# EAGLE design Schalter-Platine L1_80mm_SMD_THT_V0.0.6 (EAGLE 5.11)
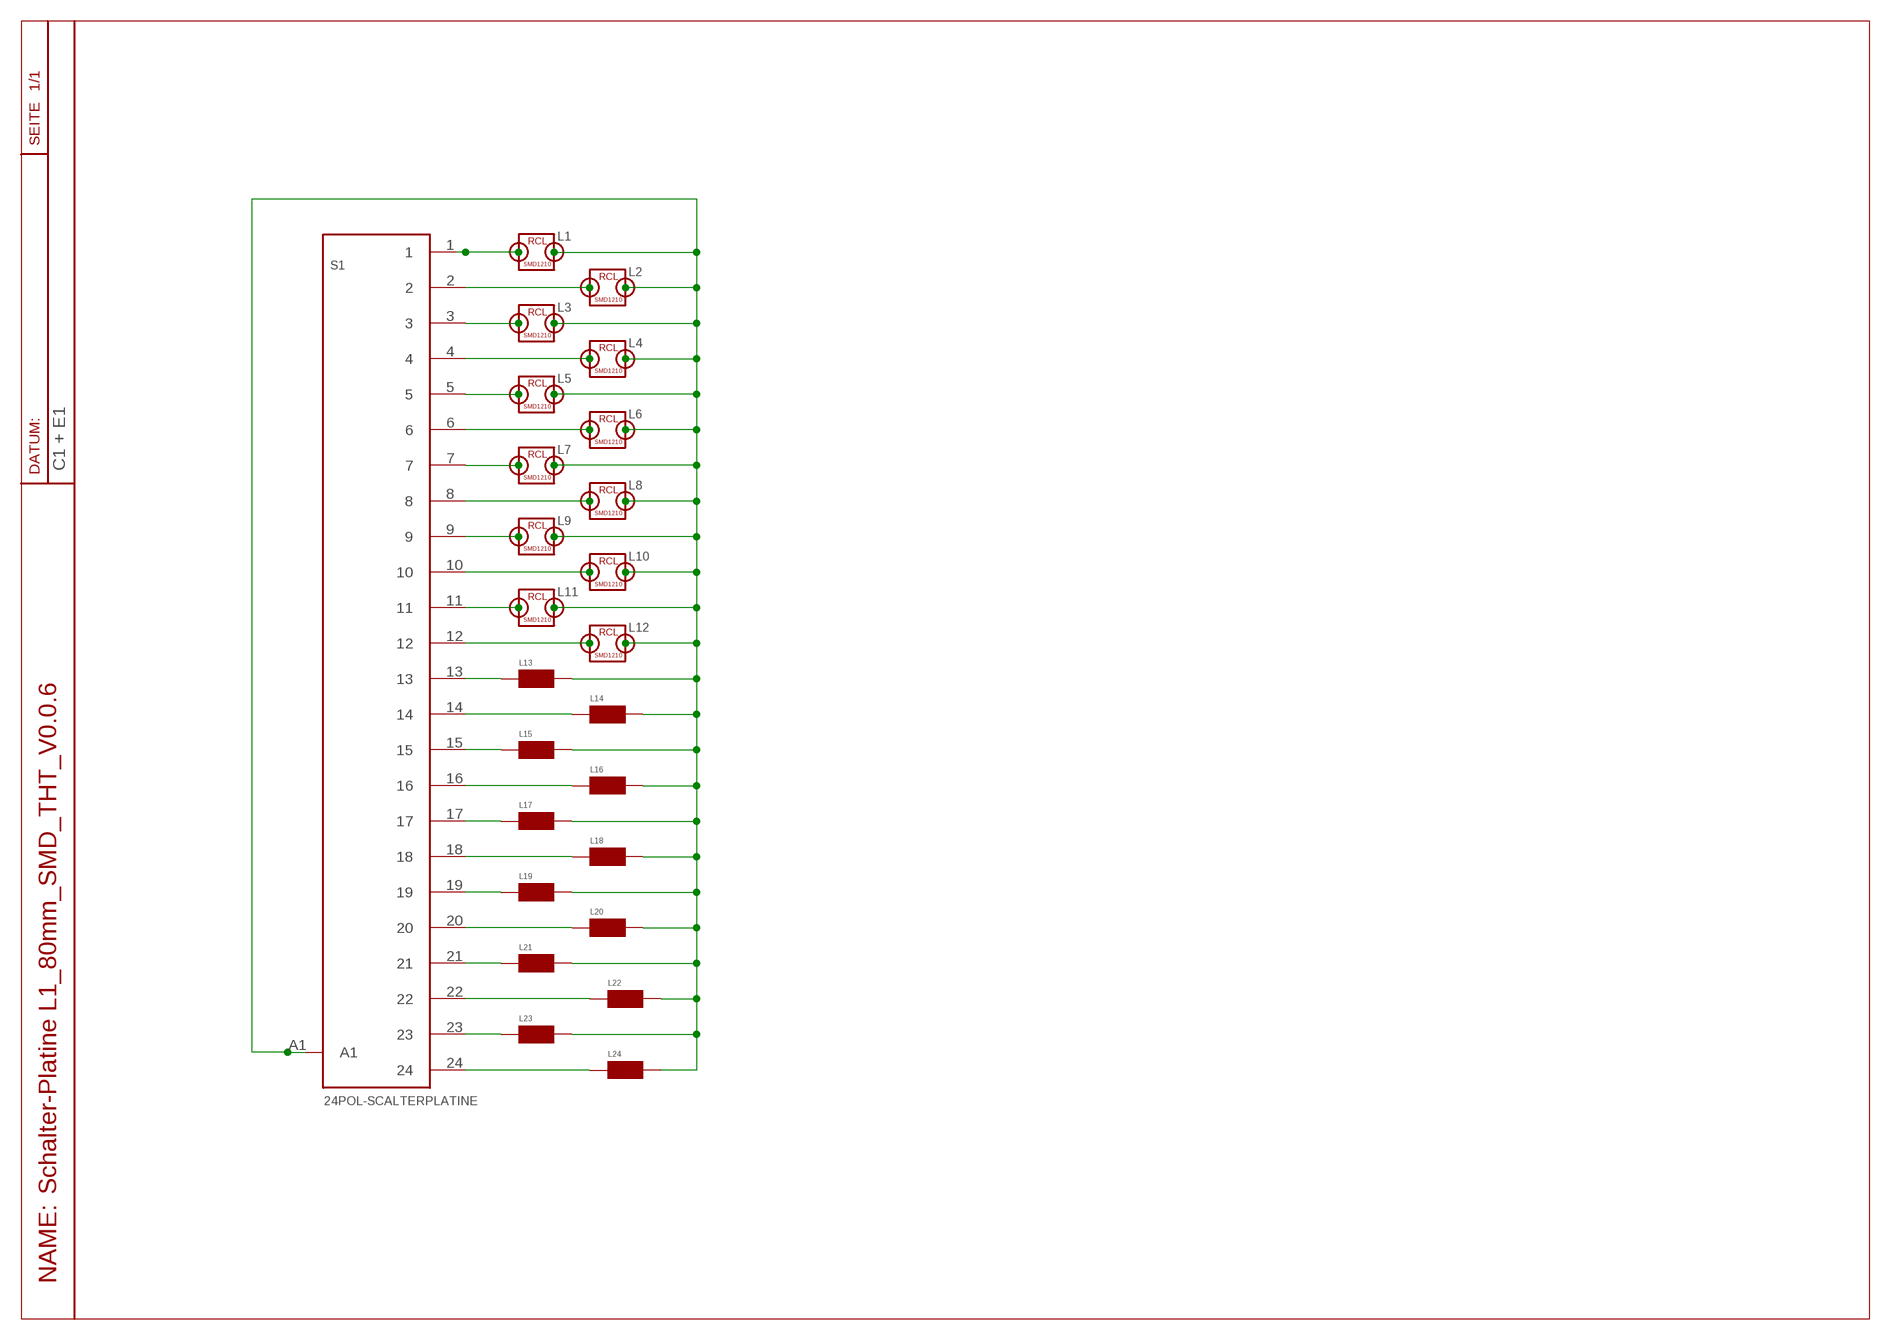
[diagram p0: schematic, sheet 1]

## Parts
L1  SMD1210U_O  [SMD1210-O_U]
L2  SMD1210U_O  [SMD1210-O_U]
L3  SMD1210U_O  [SMD1210-O_U]
L4  SMD1210U_O  [SMD1210-O_U]
L5  SMD1210U_O  [SMD1210-O_U]
L6  SMD1210U_O  [SMD1210-O_U]
L7  SMD1210U_O  [SMD1210-O_U]
L8  SMD1210U_O  [SMD1210-O_U]
L9  SMD1210U_O  [SMD1210-O_U]
L10  SMD1210U_O  [SMD1210-O_U]
L11  SMD1210U_O  [SMD1210-O_U]
L12  SMD1210U_O  [SMD1210-O_U]
L13  L5-9  [L-5-9]
L14  L5-9  [L-5-9]
L15  L5-9  [L-5-9]
L16  L5-9  [L-5-9]
L17  L5-9  [L-5-9]
L18  L5-9  [L-5-9]
L19  L5-9  [L-5-9]
L20  L5-9  [L-5-9]
L21  L5-9  [L-5-9]
L22  L5-9  [L-5-9]
L23  L5-9  [L-5-9]
L24  L5-9  [L-5-9]
S1  24POL-SCALTERPLATINE  24POL-SCALTERPLATINEGROSS  [DREHSCHALTER-GROSS]

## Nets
N$1: L1.2 L1.2U L2.2 L2.2U L3.2 L3.2U L4.2 L5.2 L6.2 L7.2 L8.2 L9.2 L10.2 L11.2 L12.2 L13.2 L14.2 L15.2 L16.2 L17.2 L18.2 L19.2 L20.2 L21.2 L22.2 L23.2 L24.2 S1.A1
N$2: L1.1(1A) L1.1U S1.1
N$3: L2.1(1A) L2.1U S1.2
N$4: L3.1(1A) L3.1U S1.3
N$5: L4.1(1A) L4.1U S1.4
N$6: L5.1(1A) L5.1U S1.5
N$7: L6.1(1A) L6.1U S1.6
N$8: L7.1(1A) L7.1U S1.7
N$9: L8.1(1A) L8.1U S1.8
N$10: L10.1(1A) L10.1U S1.10
N$11: L9.1(1A) L9.1U S1.9
N$12: L11.1(1A) L11.1U S1.11
N$13: L12.1(1A) L12.1U S1.12
N$14: L13.1 S1.13
N$15: L14.1 S1.14
N$16: L15.1 S1.15
N$17: L16.1 S1.16
N$18: L17.1 S1.17
N$19: L18.1 S1.18
N$20: L19.1 S1.19
N$21: L20.1 S1.20
N$22: L21.1 S1.21
N$23: L22.1 S1.22
N$24: L23.1 S1.23
N$25: L24.1 S1.24
Unconnected: L4.2U L5.2U L6.2U L7.2U L8.2U L9.2U L10.2U L11.2U L12.2U

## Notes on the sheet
- C1 + E1

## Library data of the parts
L1-L12 = RLC-BOX:SMD1210U_O
L13-L24 = RLC-BOX:L
S1 = RLC-BOX:24POL-SCALTERPLATINE

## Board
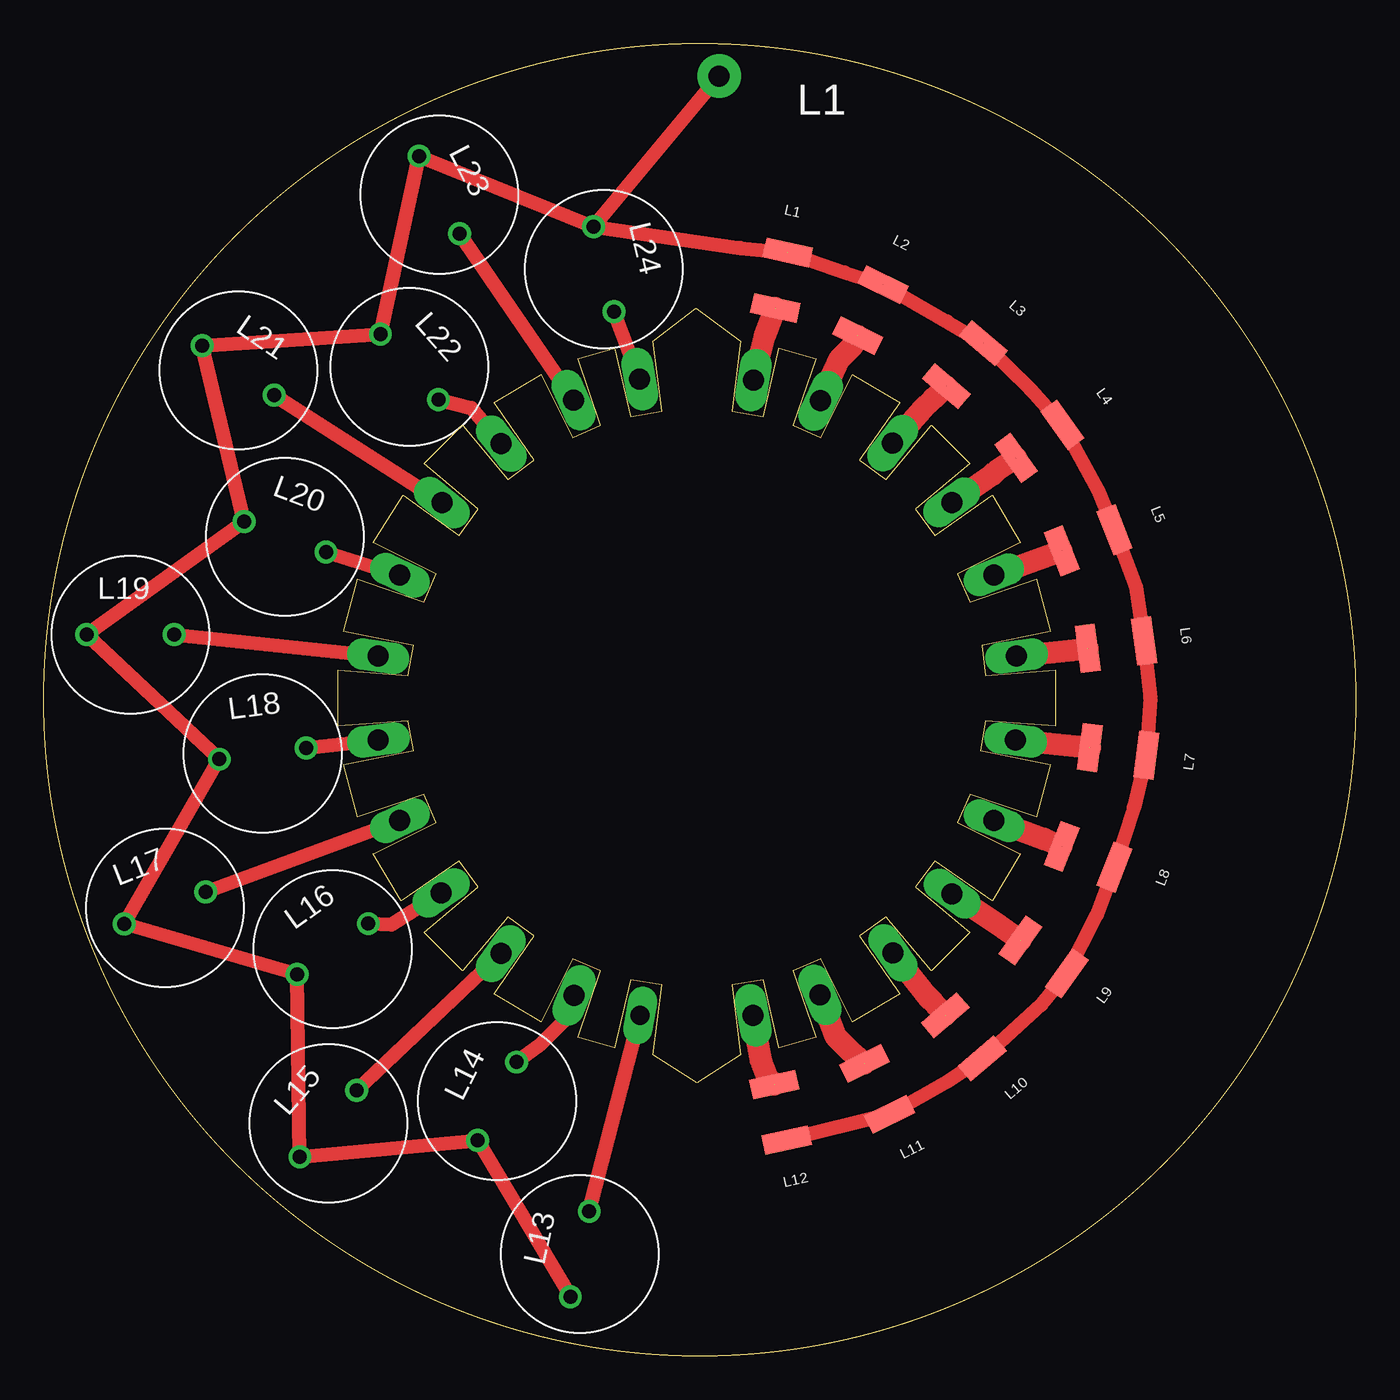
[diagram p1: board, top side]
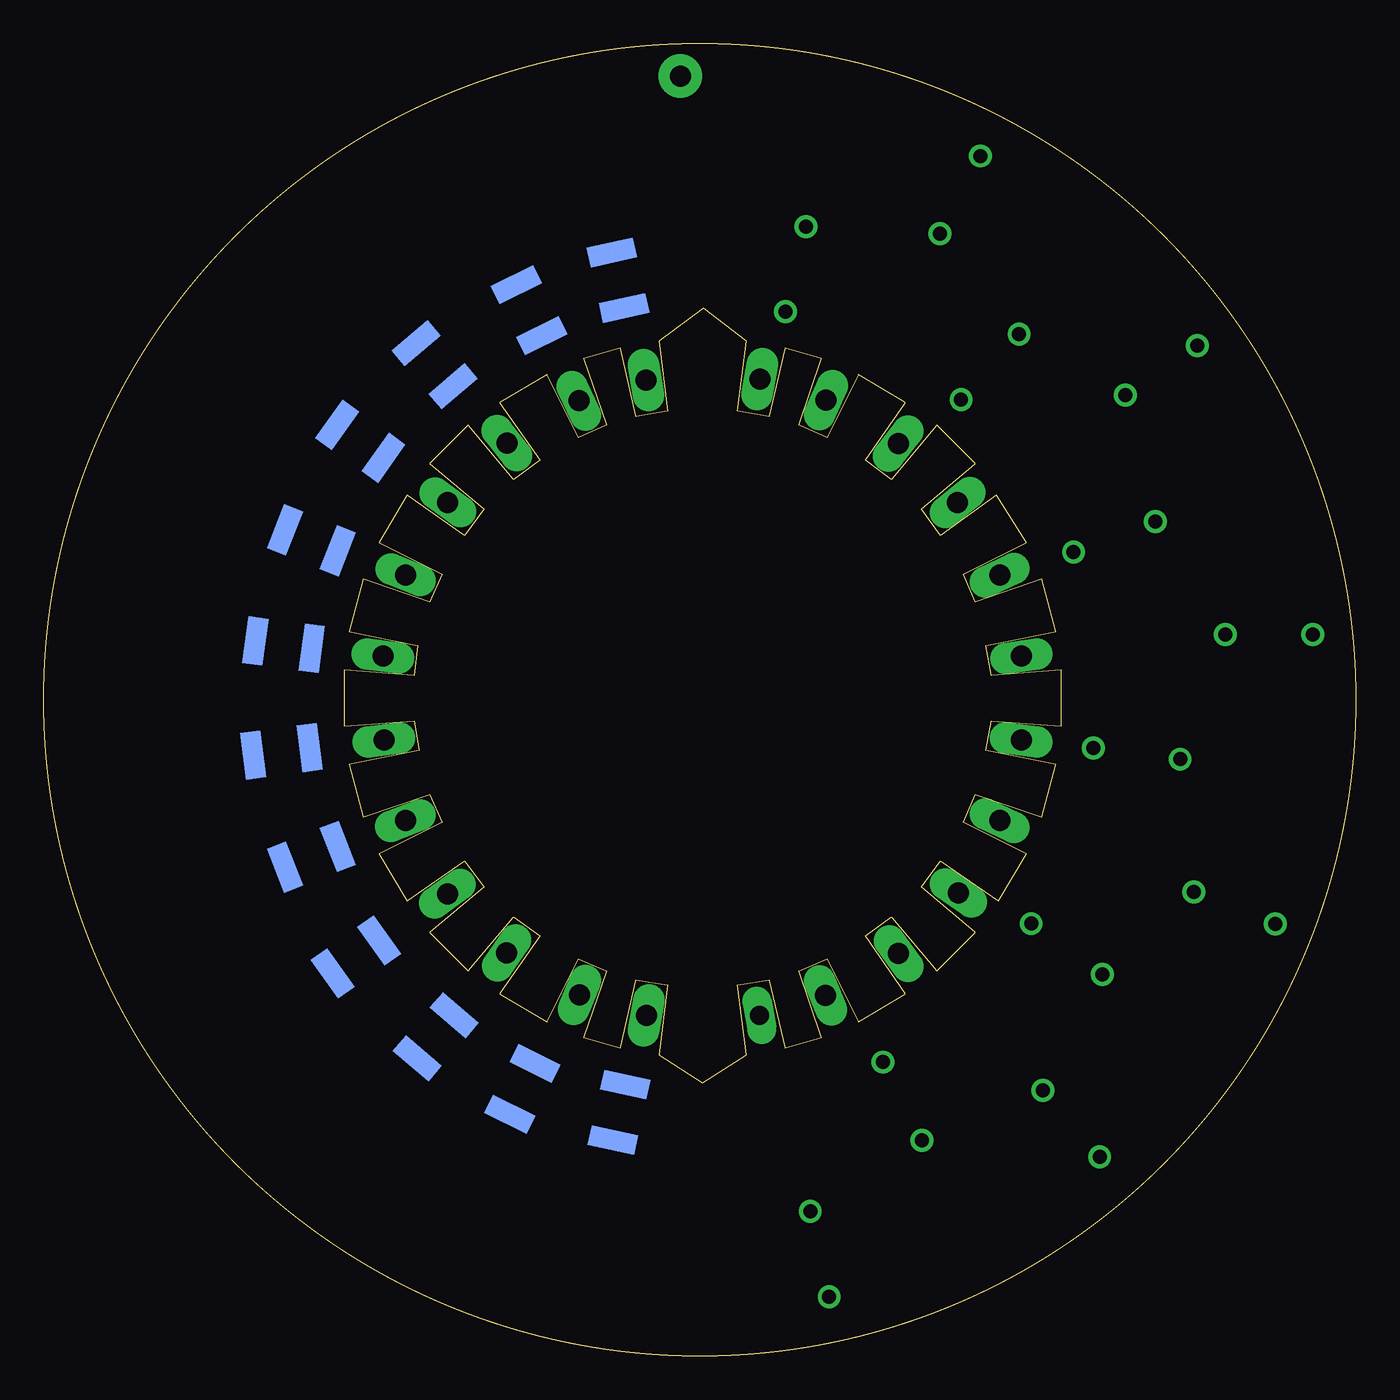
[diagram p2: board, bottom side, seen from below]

Size 75 x 75 mm. Coordinates in mm from the lower left corner, seen from the top.
Outline: circle at 37.5,37.5 radius 37.5
Copper layers (1*16): Top 0.035mm / dielectric 1.5mm / Bottom 0.035mm
Design rules "PCBWay": minimum track width 8mil, minimum drill 0.3mm, track to track 6mil, track to pad 6mil, pad to pad 6mil, via to via 6mil, smd to smd 6mil, copper to edge 40mil, drill to drill 8mil, minimum pad ring 10mil, minimum via ring 8mil, stop-mask expansion 4mil, vias tented up to drill 0mil, thermal gap 20mil

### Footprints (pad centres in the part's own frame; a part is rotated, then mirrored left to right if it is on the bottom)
SMD1210-O_U = smd 1.15 x 2.7: 1 1.625,0; 2 -1.625,0 | smd 1.15 x 2.7 bottom: 1U 1.625,0; 2U -1.625,0
L-5-9 = drill 0.8 round: 1 -2.5,0; 2 2.5,0
DREHSCHALTER-GROSS = drill 1.2 pad 1.6 long: 1 3.228,18.163; 2 7.064,16.998; 3 11.181,14.582; 4 14.562,11.184; 5 16.972,7.033; 6 18.265,2.413; 7 18.212,-2.398; 8 16.982,-7.008; 9 14.582,-11.189; 10 11.189,-14.575; 11 7.026,-16.97; 12 3.208,-18.151; 14 -7.025,-16.995; 15 -11.209,-14.607; 16 -14.62,-11.143; 17 -16.99,-7.01; 18 -18.219,-2.395; 19 -18.23,2.39; 20 -16.99,7.023; 21 -14.585,11.181; 22 -11.196,14.554; 23 -7.056,17.026; 24 -3.282,18.225 | drill 1.1 pad 1.6 long: 13 -3.256,-18.141 | drill 1.2 pad 2.5 round: A1 1.27,35.56

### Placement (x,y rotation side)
L1  42.17,61.48 257.5 top
L2  47.25,59.76 243.5 top
L3  52.65,56.65 229.5 top
L4  56.91,52.27 215.5 top
L5  59.7,46.62 201.5 top
L6  61.29,40.65 187.5 top
L7  61.41,34.55 172.5 top
L8  59.7,28.52 158.5 top
L9  57.16,22.81 144.5 top
L10  52.59,18.23 130.5 top
L11  47.63,15.25 116.5 top
L12  42.11,13.92 102.5 top
L13  30.64,5.81 257.5 top
L14  25.92,14.55 243.5 top
L15  16.27,13.28 229.5 top
L16  16.52,23.25 215.5 top
L17  6.93,25.6 201.5 top
L18  12.52,34.43 187.5 top
L19  4.96,41.22 180 top
L20  13.79,46.81 159.5 top
L21  11.12,56.33 145.5 top
L22  20.9,56.52 131.5 top
L23  22.62,66.37 117.5 top
L24  32.01,62.11 103.5 top
S1  37.34,37.6 0 top

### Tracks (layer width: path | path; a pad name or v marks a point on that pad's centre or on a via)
N$1  (3 unrouted)
  Top 0.813: L12.2 L11.2 51.7,15.69 L10.2 57.03,20.08 L9.2 60.21,25.22 L8.2 62.3,31.31 L7.2 63.26,37.6 L6.2 62.43,43.95 L5.2 60.27,49.48 L4.2 56.4,55.25 L3.2U 51.64,59.13 L2.2U 45.79,61.92 L1.2U 39.82,63.32 L24.2 | L24.2 S1.A1 | L24.2 L23.2 L22.2 L21.2 L20.2 L19.2 L18.2 L17.2 L16.2 L15.2 L14.2 L13.2
N$2  (1 unrouted)
  Top 1.27: S1.1 41.22,58.3 41.76,59.73 L1.1U
N$3  (1 unrouted)
  Top 1.27: S1.2 45.48,56.97 46.24,57.74 L2.1U
N$4  (1 unrouted)
  Top 1.27: S1.3 50.24,54.11 50.84,54.72 L3.1U
N$5  (1 unrouted)
  Top 1.27: S1.4 54.24,50.37 54.44,50.56 L4.1U
N$6  (1 unrouted)
  Top 1.27: S1.5 L5.1U
N$7  (1 unrouted)
  Top 1.27: S1.6 L6.1U
N$8  (1 unrouted)
  Top 1.27: S1.7 L7.1U
N$9  (1 unrouted)
  Top 1.27: S1.8 57.16,29.54 57.18,29.56 L8.1U
N$10  (1 unrouted)
  Top 1.27: L10.1U 50.78,20.3 50.49,20.58 S1.10
N$11  (1 unrouted)
  Top 1.27: L9.1U 54.56,24.64 54.56,24.65 S1.9
N$12  (1 unrouted)
  Top 1.27: L11.1U 46.18,17.34 45.29,18.23 S1.11
N$13  (1 unrouted)
  Top 1.27: L12.1U 41.41,15.82 41.03,16.77 S1.12
N$14
  Top 0.813: L13.1 S1.13
N$15
  Top 0.813: L14.1 28.39,17.79 30.32,19.71 S1.14
N$16
  Top 0.813: L15.1 S1.15
N$17
  Top 0.813: L16.1 19.88,24.65 S1.16
N$18
  Top 0.813: L17.1 S1.17
N$19
  Top 0.813: L18.1 S1.18
N$20
  Top 0.813: L19.1 S1.19
N$21
  Top 0.813: L20.1 S1.20
N$22
  Top 0.813: L21.1 S1.21
N$23
  Top 0.813: L22.1 24.46,54.18 S1.22
N$24
  Top 0.813: S1.23 L23.1
N$25
  Top 0.813: S1.24 L24.1

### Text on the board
tNames: L1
